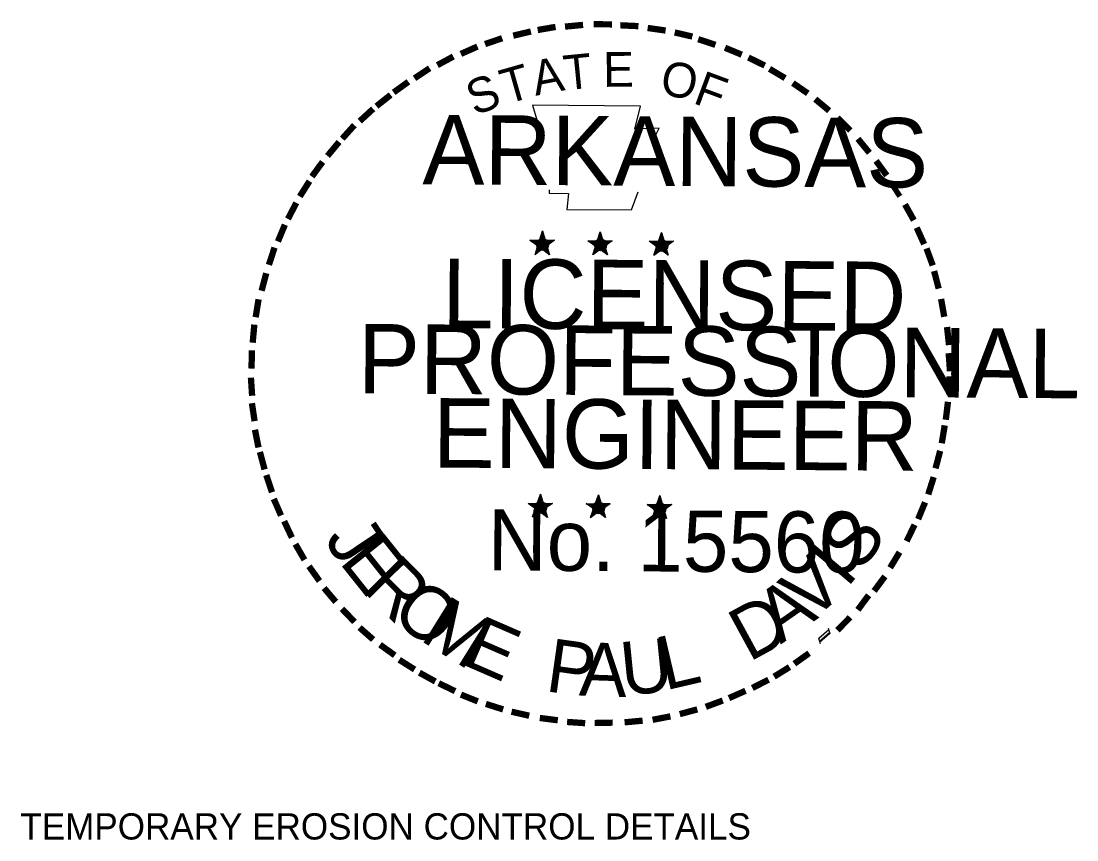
# Model space of a CAD drawing. Extents: x -3.6 to 32.1, y -0.4 to 25.6.
# Drawn here: x 27.155 to 32.083, y 21.741 to 25.561 of the extents above; entities that cross this region are included whole.
import ezdxf

# ---------------------------------------------------------------- set-up
doc = ezdxf.new("R2010")
doc.units = 0
doc.layers.add('Level 49', color=7, linetype='Continuous')
doc.layers.add('TYPICAL FONT', color=7, linetype='Continuous')

msp = doc.modelspace()

# ---------------------------------------------------------------- linework, layer by layer
at = {"layer": 'Level 49'}
for p, q in [((29.588, 24.5824), (29.58, 24.5384)), ((29.588, 24.5824), (29.58, 24.5424)), ((29.588, 24.5824), (29.584, 24.5424)), ((29.588, 24.5204), (29.588, 24.5824)), ((29.588, 24.5824), (29.598, 24.5384)), ((29.588, 24.5824), (29.596, 24.5424)), ((29.588, 24.5824), (29.59, 24.5424)), ((29.858, 24.5784), (29.85, 24.5364)), ((29.858, 24.5784), (29.85, 24.5384)), ((29.858, 24.5784), (29.852, 24.5384)), ((29.858, 24.5204), (29.858, 24.5784)), ((29.858, 24.5784), (29.868, 24.5364)), ((29.858, 24.5784), (29.866, 24.5384)), ((29.858, 24.5784), (29.86, 24.5384)), ((30.144, 24.5744), (30.134, 24.5364)), ((30.144, 24.5744), (30.14, 24.5344)), ((30.144, 24.5744), (30.14, 24.5344)), ((30.144, 24.5144), (30.144, 24.5744)), ((30.144, 24.5744), (30.156, 24.5344)), ((30.144, 24.5744), (30.152, 24.5344)), ((30.144, 24.5744), (30.148, 24.5344)), ((29.53, 24.5384), (29.588, 24.5204)), ((29.53, 24.5384), (29.572, 24.5364)), ((29.53, 24.5384), (29.572, 24.5344)), ((29.53, 24.5384), (29.568, 24.5284)), ((29.53, 24.5384), (29.568, 24.5224)), ((29.53, 24.5384), (29.568, 24.5204)), ((29.53, 24.5384), (29.568, 24.5144)), ((29.554, 24.4724), (29.588, 24.5204)), ((29.554, 24.4724), (29.568, 24.5184)), ((29.554, 24.4724), (29.572, 24.5124)), ((29.554, 24.4724), (29.574, 24.5104)), ((29.554, 24.4724), (29.58, 24.5064)), ((29.554, 24.4724), (29.588, 24.5064)), ((29.554, 24.4724), (29.588, 24.5024)), ((29.644, 24.5384), (29.588, 24.5204)), ((29.622, 24.4704), (29.588, 24.5204)), ((29.622, 24.4704), (29.588, 24.5064)), ((29.622, 24.4704), (29.588, 24.5024)), ((29.644, 24.5384), (29.592, 24.5344)), ((29.622, 24.4704), (29.592, 24.5064)), ((29.644, 24.5384), (29.598, 24.5304)), ((29.644, 24.5384), (29.598, 24.5264)), ((29.622, 24.4704), (29.598, 24.5184)), ((29.622, 24.4704), (29.598, 24.5124)), ((29.622, 24.4704), (29.604, 24.5204)), ((29.644, 24.5384), (29.606, 24.5264)), ((29.644, 24.5384), (29.612, 24.5224)), ((29.644, 24.5384), (29.614, 24.5204)), ((29.8, 24.5364), (29.858, 24.5204)), ((29.8, 24.5364), (29.842, 24.5344)), ((29.8, 24.5364), (29.842, 24.5304)), ((29.8, 24.5364), (29.842, 24.5284)), ((29.8, 24.5364), (29.84, 24.5204)), ((29.8, 24.5364), (29.84, 24.5184)), ((29.8, 24.5364), (29.84, 24.5124)), ((29.824, 24.4704), (29.858, 24.5204)), ((29.824, 24.4704), (29.842, 24.5144)), ((29.824, 24.4704), (29.842, 24.5124)), ((29.824, 24.4704), (29.844, 24.5104)), ((29.824, 24.4704), (29.85, 24.5044)), ((29.824, 24.4704), (29.858, 24.5044)), ((29.824, 24.4704), (29.858, 24.5024)), ((29.914, 24.5364), (29.858, 24.5204)), ((29.892, 24.4704), (29.858, 24.5204)), ((29.892, 24.4704), (29.858, 24.5044)), ((29.892, 24.4704), (29.858, 24.5024)), ((29.914, 24.5364), (29.864, 24.5344)), ((29.892, 24.4704), (29.864, 24.5044)), ((29.914, 24.5364), (29.868, 24.5284)), ((29.914, 24.5364), (29.868, 24.5264)), ((29.892, 24.4704), (29.868, 24.5184)), ((29.892, 24.4704), (29.868, 24.5104)), ((29.892, 24.4704), (29.874, 24.5184)), ((29.914, 24.5364), (29.876, 24.5224)), ((29.914, 24.5364), (29.882, 24.5204)), ((29.914, 24.5364), (29.884, 24.5184)), ((30.086, 24.5344), (30.144, 24.5144)), ((30.086, 24.5344), (30.132, 24.5284)), ((30.086, 24.5344), (30.128, 24.5264)), ((30.086, 24.5344), (30.128, 24.5224)), ((30.086, 24.5344), (30.126, 24.5184)), ((30.086, 24.5344), (30.126, 24.5124)), ((30.086, 24.5344), (30.126, 24.5124)), ((30.108, 24.4684), (30.144, 24.5144)), ((30.108, 24.4684), (30.128, 24.5124)), ((30.108, 24.4684), (30.132, 24.5064)), ((30.108, 24.4684), (30.132, 24.5044)), ((30.108, 24.4684), (30.144, 24.5044)), ((30.108, 24.4684), (30.14, 24.5024)), ((30.108, 24.4684), (30.148, 24.4964)), ((30.2, 24.5344), (30.144, 24.5144)), ((30.176, 24.4684), (30.144, 24.5144)), ((30.176, 24.4684), (30.144, 24.5044)), ((30.176, 24.4684), (30.144, 24.4964)), ((30.2, 24.5344), (30.15, 24.5284)), ((30.176, 24.4684), (30.15, 24.5024)), ((30.2, 24.5344), (30.156, 24.5264)), ((30.2, 24.5344), (30.156, 24.5204)), ((30.176, 24.4684), (30.156, 24.5124)), ((30.176, 24.4684), (30.156, 24.5064)), ((30.176, 24.4684), (30.16, 24.5124)), ((30.2, 24.5344), (30.164, 24.5184)), ((30.2, 24.5344), (30.166, 24.5184)), ((30.2, 24.5344), (30.172, 24.5144)), ((29.58, 23.3544), (29.568, 23.3144)), ((29.58, 23.3544), (29.572, 23.3104)), ((29.58, 23.3544), (29.574, 23.3104)), ((29.58, 23.2924), (29.58, 23.3544)), ((29.58, 23.3544), (29.588, 23.3104)), ((29.58, 23.3544), (29.588, 23.3104)), ((29.58, 23.3544), (29.58, 23.3104)), ((29.85, 23.3504), (29.84, 23.3104)), ((29.85, 23.3504), (29.842, 23.3104)), ((29.85, 23.3504), (29.844, 23.3104)), ((29.85, 23.2924), (29.85, 23.3504)), ((29.85, 23.3504), (29.858, 23.3084)), ((29.85, 23.3504), (29.858, 23.3084)), ((29.85, 23.3504), (29.85, 23.3104)), ((30.136, 23.3484), (30.126, 23.3064)), ((30.136, 23.3484), (30.128, 23.3064)), ((30.136, 23.3484), (30.132, 23.3064)), ((30.136, 23.2864), (30.136, 23.3484)), ((30.136, 23.3484), (30.144, 23.3064)), ((30.136, 23.3484), (30.144, 23.3064)), ((30.136, 23.3484), (30.136, 23.3064)), ((29.522, 23.3104), (29.58, 23.2924)), ((29.522, 23.3104), (29.564, 23.3084)), ((29.522, 23.3104), (29.562, 23.3024)), ((29.522, 23.3104), (29.562, 23.3024)), ((29.522, 23.3104), (29.562, 23.2944)), ((29.522, 23.3104), (29.562, 23.2924)), ((29.522, 23.3104), (29.562, 23.2904)), ((29.542, 23.2484), (29.58, 23.2924)), ((29.542, 23.2484), (29.562, 23.2924)), ((29.542, 23.2484), (29.564, 23.2844)), ((29.542, 23.2484), (29.566, 23.2844)), ((29.542, 23.2484), (29.58, 23.2824)), ((29.542, 23.2484), (29.572, 23.2784)), ((29.542, 23.2484), (29.58, 23.2764)), ((29.612, 23.2444), (29.576, 23.2764)), ((29.636, 23.3104), (29.58, 23.2924)), ((29.612, 23.2444), (29.58, 23.2924)), ((29.612, 23.2444), (29.58, 23.2784)), ((29.612, 23.2444), (29.582, 23.2784)), ((29.636, 23.3104), (29.584, 23.3084)), ((29.636, 23.3104), (29.588, 23.3024)), ((29.636, 23.3104), (29.588, 23.3004)), ((29.612, 23.2444), (29.588, 23.2924)), ((29.612, 23.2444), (29.588, 23.2844)), ((29.636, 23.3104), (29.596, 23.2984)), ((29.612, 23.2444), (29.596, 23.2924)), ((29.636, 23.3104), (29.6, 23.2944)), ((29.636, 23.3104), (29.604, 23.2924)), ((29.792, 23.3104), (29.85, 23.2924)), ((29.792, 23.3104), (29.834, 23.3064)), ((29.792, 23.3104), (29.834, 23.3024)), ((29.792, 23.3104), (29.834, 23.3004)), ((29.792, 23.3104), (29.832, 23.2944)), ((29.792, 23.3104), (29.832, 23.2904)), ((29.792, 23.3104), (29.832, 23.2864)), ((29.812, 23.2444), (29.85, 23.2924)), ((29.812, 23.2444), (29.834, 23.2904)), ((29.812, 23.2444), (29.834, 23.2824)), ((29.812, 23.2444), (29.836, 23.2824)), ((29.812, 23.2444), (29.842, 23.2784)), ((29.812, 23.2444), (29.85, 23.2784)), ((29.812, 23.2444), (29.85, 23.2744)), ((29.882, 23.2444), (29.848, 23.2744)), ((29.904, 23.3084), (29.85, 23.2924)), ((29.882, 23.2444), (29.85, 23.2924)), ((29.882, 23.2444), (29.85, 23.2784)), ((29.882, 23.2444), (29.852, 23.2784)), ((29.904, 23.3084), (29.856, 23.3084)), ((29.904, 23.3084), (29.858, 23.3004)), ((29.904, 23.3084), (29.858, 23.3004)), ((29.882, 23.2444), (29.858, 23.2904)), ((29.882, 23.2444), (29.858, 23.2844)), ((29.904, 23.3084), (29.866, 23.2944)), ((29.882, 23.2444), (29.866, 23.2904)), ((29.904, 23.3084), (29.872, 23.2924)), ((29.904, 23.3084), (29.874, 23.2904)), ((30.078, 23.3064), (30.136, 23.2864)), ((30.078, 23.3064), (30.12, 23.3024)), ((30.078, 23.3064), (30.12, 23.2984)), ((30.078, 23.3064), (30.118, 23.2944)), ((30.078, 23.3064), (30.118, 23.2904)), ((30.078, 23.3064), (30.116, 23.2864)), ((30.078, 23.3064), (30.116, 23.2824)), ((30.1, 23.2404), (30.136, 23.2864)), ((30.1, 23.2404), (30.118, 23.2864)), ((30.1, 23.2404), (30.12, 23.2784)), ((30.1, 23.2404), (30.124, 23.2784)), ((30.1, 23.2404), (30.128, 23.2744)), ((30.1, 23.2404), (30.134, 23.2744)), ((30.1, 23.2404), (30.136, 23.2704)), ((30.168, 23.2404), (30.134, 23.2744)), ((30.168, 23.2404), (30.134, 23.2704)), ((30.192, 23.3064), (30.136, 23.2864)), ((30.168, 23.2404), (30.136, 23.2864)), ((30.168, 23.2404), (30.14, 23.2744)), ((30.192, 23.3064), (30.142, 23.3024)), ((30.192, 23.3064), (30.144, 23.2984)), ((30.192, 23.3064), (30.144, 23.2944)), ((30.168, 23.2404), (30.144, 23.2784)), ((30.168, 23.2404), (30.148, 23.2864)), ((30.168, 23.2404), (30.15, 23.2864)), ((30.192, 23.3064), (30.156, 23.2924)), ((30.192, 23.3064), (30.158, 23.2864)), ((30.192, 23.3064), (30.16, 23.2864))]:
    msp.add_line(p, q, dxfattribs=at)
for points in [[(29.542, 25.1684), (29.582, 25.0324)], [(30.11, 25.0144), (30.134, 25.0624), (30.02, 25.0564), (30.046, 25.1644), (29.542, 25.1684)], [(29.62, 24.7744), (29.62, 24.7584), (29.71, 24.7564), (29.702, 24.6824), (30.004, 24.6804), (30.036, 24.7644)], [(29.588, 24.5824), (29.622, 24.4704), (29.53, 24.5384), (29.644, 24.5384), (29.554, 24.4724), (29.588, 24.5824)], [(29.858, 24.5784), (29.892, 24.4704), (29.8, 24.5364), (29.914, 24.5364), (29.824, 24.4704), (29.858, 24.5784)], [(30.144, 24.5744), (30.176, 24.4684), (30.086, 24.5344), (30.2, 24.5344), (30.108, 24.4684), (30.144, 24.5744)], [(29.58, 23.3544), (29.612, 23.2444), (29.522, 23.3104), (29.636, 23.3104), (29.542, 23.2484), (29.58, 23.3544)], [(29.85, 23.3504), (29.882, 23.2444), (29.792, 23.3104), (29.904, 23.3084), (29.812, 23.2444), (29.85, 23.3504)], [(30.136, 23.3484), (30.168, 23.2404), (30.078, 23.3064), (30.192, 23.3064), (30.1, 23.2404), (30.136, 23.3484)], [(30.886, 22.6564), (30.878, 22.6824), (30.926, 22.7224)], [(30.922, 22.7284), (30.93, 22.7044), (30.882, 22.6624)], [(30.93, 22.7084), (30.882, 22.6664)], [(30.93, 22.7044), (30.884, 22.6644)]]:
    msp.add_lwpolyline(points, dxfattribs=at)
for centre, radius in [((29.589, 24.5194), 0.0279), ((29.589, 24.5194), 0.0253), ((29.8595, 24.5175), 0.0279), ((29.589, 24.5194), 0.0234), ((29.589, 24.5194), 0.0215), ((29.589, 24.5194), 0.0188), ((29.589, 24.5194), 0.0174), ((29.589, 24.5194), 0.0161), ((29.589, 24.5194), 0.0138), ((29.589, 24.5194), 0.0121), ((29.589, 24.5194), 0.0101), ((29.589, 24.5194), 0.00803), ((29.589, 24.5194), 0.00599), ((29.589, 24.5194), 0.0048), ((29.589, 24.5194), 0.00234), ((29.8595, 24.5175), 0.0253), ((29.8595, 24.5175), 0.0234), ((29.8595, 24.5175), 0.0215), ((29.8595, 24.5175), 0.0188), ((29.8595, 24.5175), 0.0174), ((29.8595, 24.5175), 0.0161), ((29.8595, 24.5175), 0.0138), ((29.8595, 24.5175), 0.0121), ((29.8595, 24.5175), 0.0101), ((29.8595, 24.5175), 0.00803), ((29.8595, 24.5175), 0.00599), ((29.8595, 24.5175), 0.0048), ((29.8595, 24.5175), 0.00234), ((30.1458, 24.5137), 0.0279), ((30.1458, 24.5137), 0.0253), ((30.1458, 24.5137), 0.0234), ((30.1458, 24.5137), 0.0215), ((30.1458, 24.5137), 0.0188), ((30.1458, 24.5137), 0.0174), ((30.1458, 24.5137), 0.0161), ((30.1458, 24.5137), 0.0138), ((30.1458, 24.5137), 0.0121), ((30.1458, 24.5137), 0.0101), ((30.1458, 24.5137), 0.00803), ((30.1458, 24.5137), 0.00599), ((30.1458, 24.5137), 0.0048), ((30.1458, 24.5137), 0.00234), ((29.5798, 23.2924), 0.0279), ((29.5798, 23.2924), 0.0253), ((29.5798, 23.2924), 0.0234), ((29.5798, 23.2924), 0.0215), ((29.8503, 23.2905), 0.0279), ((29.8503, 23.2905), 0.0253), ((29.8503, 23.2905), 0.0234), ((29.8503, 23.2905), 0.0215), ((30.1366, 23.2866), 0.0279), ((30.1366, 23.2866), 0.0253), ((29.5798, 23.2924), 0.0188), ((29.5798, 23.2924), 0.0174), ((29.5798, 23.2924), 0.0161), ((29.5798, 23.2924), 0.0138), ((29.5798, 23.2924), 0.0121), ((29.5798, 23.2924), 0.0101), ((29.5798, 23.2924), 0.00803), ((29.5798, 23.2924), 0.00599), ((29.5798, 23.2924), 0.0048), ((29.5798, 23.2924), 0.00234), ((29.8503, 23.2905), 0.0188), ((29.8503, 23.2905), 0.0174), ((29.8503, 23.2905), 0.0161), ((29.8503, 23.2905), 0.0138), ((29.8503, 23.2905), 0.0121), ((29.8503, 23.2905), 0.0101), ((29.8503, 23.2905), 0.00803), ((29.8503, 23.2905), 0.00599), ((29.8503, 23.2905), 0.0048), ((29.8503, 23.2905), 0.00234), ((30.1366, 23.2866), 0.0234), ((30.1366, 23.2866), 0.0215), ((30.1366, 23.2866), 0.0188), ((30.1366, 23.2866), 0.0174), ((30.1366, 23.2866), 0.0161), ((30.1366, 23.2866), 0.0138), ((30.1366, 23.2866), 0.0121), ((30.1366, 23.2866), 0.0101), ((30.1366, 23.2866), 0.00803), ((30.1366, 23.2866), 0.00599), ((30.1366, 23.2866), 0.0048), ((30.1366, 23.2866), 0.00234)]:
    msp.add_circle(centre, radius, dxfattribs=at)

# ---------------------------------------------------------------- texts
for s, height, rotation, p in [('-', 0.2593, 9.8217, (29.568, 25.4184)), ('-', 0.2592, 5.4992, (29.688, 25.4344)), ('-', 0.2592, 359.7886, (29.812, 25.4464)), ('-', 0.2593, 357.3454, (29.932, 25.4424)), ('-', 0.2593, 351.7641, (30.05, 25.4324)), ('-', 0.2592, 18.7785, (29.338, 25.3544)), ('-', 0.2592, 13.2326, (29.46, 25.3924)), ('-', 0.2593, 346.8073, (30.168, 25.4144)), ('-', 0.2593, 341.9386, (30.27, 25.3864)), ('-', 0.2592, 23.9096, (29.234, 25.3104)), ('-', 0.2593, 337.4575, (30.388, 25.3504)), ('-', 0.2592, 28.3942, (29.132, 25.2604)), ('A', 0.162, 10.8156, (29.556, 25.2124)), ('T', 0.162, 5.6252, (29.694, 25.2384)), ('E', 0.162, 0.4347, (29.872, 25.2544)), ('-', 0.2592, 333.7235, (30.492, 25.3084)), ('-', 0.2593, 33.666, (29.034, 25.2024)), ('T', 0.162, 16.006, (29.42, 25.1724)), ('O', 0.162, 350.0539, (30.132, 25.2204)), ('-', 0.2592, 329.2433, (30.584, 25.2604)), ('-', 0.2592, 35.8341, (28.94, 25.1384)), ('S', 0.162, 21.1964, (29.272, 25.1184)), ('F', 0.162, 339.6731, (30.286, 25.1804)), ('-', 0.2592, 325.4651, (30.688, 25.1984)), ('-', 0.2592, 38.5531, (28.864, 25.0764)), ('-', 0.2593, 320.1321, (30.786, 25.1304)), ('-', 0.2592, 42.5646, (28.792, 25.0104)), ('ARKANSAS', 0.32407, 359.6024, (29.028, 24.8004)), ('-', 0.2593, 315.181, (30.884, 25.0504)), ('-', 0.2593, 48.0254, (28.718, 24.9344)), ('-', 0.2592, 50.2166, (28.652, 24.8564)), ('-', 0.2592, 309.4821, (30.974, 24.9604)), ('-', 0.2593, 53.8349, (28.584, 24.7644)), ('-', 0.2592, 306.2546, (31.056, 24.8624)), ('-', 0.2592, 57.673, (28.532, 24.6764)), ('-', 0.2268, 303.2777, (31.136, 24.7684)), ('-', 0.2592, 62.4738, (28.482, 24.5784)), ('-', 0.2593, 299.2708, (31.186, 24.6704)), ('-', 0.2592, 67.3767, (28.44, 24.4804)), ('-', 0.2592, 294.2652, (31.238, 24.5704)), ('-', 0.2592, 71.9969, (28.402, 24.3784)), ('-', 0.2592, 290.1752, (31.282, 24.4804)), ('LICENSED', 0.32407, 359.6024, (29.1187, 24.129)), ('-', 0.2592, 284.7257, (31.316, 24.3844)), ('-', 0.2593, 75.0634, (28.37, 24.2624)), ('-', 0.2592, 80.8037, (28.346, 24.1484)), ('-', 0.2593, 280.1517, (31.348, 24.2624)), ('-', 0.2592, 84.7887, (28.334, 24.0364)), ('PROFESSIONAL', 0.324072, 359.6024, (28.726, 23.8244)), ('-', 0.2593, 276.1986, (31.376, 24.1384)), ('-', 0.2593, 88.6646, (28.33, 23.9224)), ('-', 0.2593, 273.9325, (31.384, 24.0204)), ('-', 0.2592, 269.5431, (31.388, 23.9204)), ('-', 0.2592, 93.7983, (28.334, 23.8044)), ('-', 0.2592, 98.5503, (28.346, 23.6944)), ('ENGINEER', 0.32407, 359.6024, (29.076, 23.4784)), ('-', 0.2592, 263.1196, (31.384, 23.8124)), ('-', 0.2592, 101.3173, (28.364, 23.5764)), ('-', 0.2593, 260.5977, (31.37, 23.7064)), ('-', 0.2592, 255.365, (31.352, 23.5964)), ('-', 0.2592, 105.0602, (28.392, 23.4804)), ('-', 0.2592, 108.6898, (28.426, 23.3804)), ('-', 0.2593, 252.4705, (31.324, 23.4784)), ('-', 0.2592, 113.6667, (28.466, 23.2804)), ('-', 0.2592, 247.4911, (31.288, 23.3684)), ('No. 15560', 0.28517, 359.6024, (29.332, 22.9988)), ('S', 0.2496, 53.5227, (31.0701, 22.9834)), ('-', 0.2592, 115.3313, (28.516, 23.1804)), ('J', 0.2496, 303.9209, (28.5653, 23.1421)), ('-', 0.2593, 244.2221, (31.242, 23.2684)), ('E', 0.2496, 308.618, (28.6356, 23.0376)), ('-', 0.2593, 120.0495, (28.572, 23.0844)), ('I', 0.2496, 49.9999, (31.0087, 22.9117)), ('R', 0.2496, 314.7784, (28.7402, 22.91)), ('V', 0.2496, 41.4844, (30.843, 22.755)), ('-', 0.2593, 238.6736, (31.178, 23.1484)), ('-', 0.2592, 125.4958, (28.638, 22.9944)), ('-', 0.2593, 233.4476, (31.116, 23.0424)), ('-', 0.2592, 130.3205, (28.71, 22.9044)), ('O', 0.2496, 321.6761, (28.8729, 22.7814)), ('A', 0.2496, 34.8903, (30.6998, 22.6516)), ('M', 0.2496, 328.1357, (29.0103, 22.6762)), ('-', 0.2593, 233.4476, (31.04, 22.9544)), ('-', 0.2593, 133.8262, (28.794, 22.8164)), ('D', 0.2496, 28.5809, (30.5525, 22.5686)), ('E', 0.2496, 336.4966, (29.2041, 22.5641)), ('-', 0.2592, 225.3677, (30.964, 22.8604)), ('-', 0.2592, 138.5362, (28.876, 22.7404)), ('P', 0.2496, 351.9783, (29.5973, 22.4355)), ('U', 0.2496, 5.7635, (29.9652, 22.4132)), ('L', 0.2496, 13.0992, (30.1602, 22.4374)), ('-', 0.2592, 144.2487, (28.97, 22.6744)), ('A', 0.2496, 357.9896, (29.757, 22.4149)), ('-', 0.2592, 215.3387, (30.788, 22.7024)), ('-', 0.2593, 147.6922, (29.058, 22.6124)), ('-', 0.2592, 151.1728, (29.15, 22.5604)), ('-', 0.2593, 211.8515, (30.702, 22.6404)), ('-', 0.2592, 154.2026, (29.238, 22.5184)), ('-', 0.2593, 206.9592, (30.612, 22.5844)), ('-', 0.2593, 158.1636, (29.338, 22.4744)), ('-', 0.2592, 203.854, (30.51, 22.5344)), ('-', 0.2592, 162.4007, (29.45, 22.4404)), ('-', 0.2592, 200.3208, (30.41, 22.4904)), ('-', 0.2593, 167.1579, (29.564, 22.4144)), ('-', 0.2593, 190.8882, (30.182, 22.4184)), ('-', 0.2592, 195.0767, (30.3, 22.4504)), ('-', 0.2593, 172.7179, (29.688, 22.3964)), ('-', 0.2593, 176.1207, (29.81, 22.3844)), ('-', 0.2593, 181.1942, (29.93, 22.3884)), ('-', 0.2592, 185.4191, (30.062, 22.3984))]:
    msp.add_text(s, height=height, rotation=rotation, dxfattribs=at).set_placement(p)
at = {"layer": 'TYPICAL FONT'}
msp.add_text('TEMPORARY EROSION CONTROL DETAILS', height=0.122398, dxfattribs=at).set_placement((27.1511, 21.7427))

doc.saveas('drawing.dxf')
